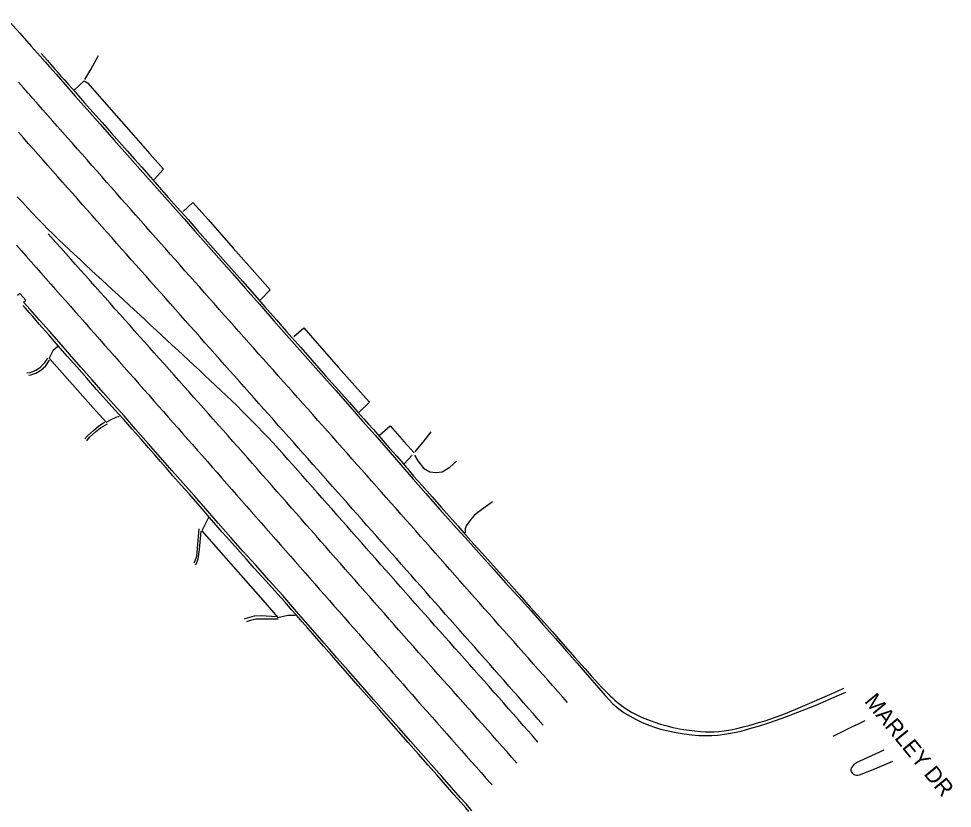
# Model space of a CAD drawing. Extents: x 1970211 to 1973046, y 801032 to 804001.
# Drawn here: x 1970390.1 to 1970705.8, y 803591.8 to 803858.6 of the extents above; entities that cross this region are included whole.
import ezdxf

# ---------------------------------------------------------------- set-up
doc = ezdxf.new("R2010")
doc.units = 0
for name, color, linetype in [('RD_EX_Conc', 7, 'Continuous'), ('RD_EX_Road', 7, 'Continuous'), ('RD_EX_Road_Paint', 7, 'Continuous'), ('RD_TX_RoadID', 7, 'Continuous')]:
    doc.layers.add(name, color=color, linetype=linetype)

msp = doc.modelspace()

# ---------------------------------------------------------------- linework, layer by layer
at = {"layer": 'RD_EX_Conc'}
for points in [[(1970397.74, 803846.86), (1970399.84, 803844.44), (1970400.97, 803843.15), (1970401.68, 803842.35), (1970402.51, 803841.4), (1970403.45, 803840.35), (1970404.45, 803839.23), (1970405.61, 803837.94), (1970407.04, 803836.34), (1970408.36, 803834.84), (1970409.23, 803833.84), (1970410.36, 803832.54), (1970412.45, 803830.16), (1970415.21, 803827.03), (1970418.35, 803823.47), (1970421.48, 803819.94), (1970424.23, 803816.85), (1970426.78, 803814), (1970429.31, 803811.14), (1970431.75, 803808.39), (1970434.01, 803805.84), (1970436.21, 803803.34), (1970438.48, 803800.75), (1970440.71, 803798.23), (1970442.77, 803795.92), (1970444.91, 803793.51), (1970447.4, 803790.7), (1970450.63, 803787.04), (1970454.98, 803782.09), (1970460.15, 803776.25), (1970465.78, 803769.88), (1970470.62, 803764.42), (1970473.38, 803761.29), (1970475.22, 803759.2), (1970477.28, 803756.84), (1970479.22, 803754.62), (1970480.69, 803752.95), (1970482.51, 803750.9), (1970485.49, 803747.52), (1970489.38, 803743.12), (1970493.92, 803737.97), (1970498.36, 803732.94), (1970501.95, 803728.88), (1970504.75, 803725.72), (1970506.79, 803723.43), (1970508.42, 803721.61), (1970509.97, 803719.87), (1970511.57, 803718.05), (1970513.36, 803716.02), (1970515.44, 803713.63), (1970517.95, 803710.76), (1970520.12, 803708.29), (1970521.16, 803707.09), (1970521.69, 803706.47), (1970522.29, 803705.71), (1970523.67, 803704.08), (1970526.52, 803700.83), (1970529.93, 803696.99), (1970532.98, 803693.55), (1970535.82, 803690.35), (1970538.6, 803687.19), (1970541.33, 803684.09), (1970544.04, 803681.09), (1970546.8, 803678.06), (1970549.7, 803674.86), (1970552.75, 803671.45), (1970555.98, 803667.82), (1970559.42, 803663.94), (1970563.1, 803659.8), (1970566.85, 803655.59), (1970570.46, 803651.51), (1970574.16, 803647.33), (1970578.16, 803642.81), (1970581.61, 803638.89), (1970583.69, 803636.56), (1970585, 803635.11), (1970586.15, 803633.87), (1970587.2, 803632.78), (1970588.18, 803631.76), (1970589.12, 803630.8), (1970590.01, 803629.92), (1970590.86, 803629.11), (1970591.67, 803628.36), (1970592.63, 803627.55), (1970593.92, 803626.53), (1970595.49, 803625.42), (1970597.31, 803624.33), (1970599.18, 803623.34), (1970600.94, 803622.53), (1970602.76, 803621.78), (1970604.83, 803621), (1970607.08, 803620.26), (1970609.4, 803619.62), (1970611.35, 803619.15), (1970612.52, 803618.88), (1970613.54, 803618.7), (1970615.05, 803618.45), (1970616.87, 803618.19), (1970618.79, 803617.98), (1970620.68, 803617.81), (1970622.4, 803617.69), (1970623.94, 803617.63), (1970625.29, 803617.66), (1970626.76, 803617.78), (1970628.64, 803618.02), (1970630.78, 803618.37), (1970632.99, 803618.81), (1970635.13, 803619.31), (1970637.05, 803619.8), (1970638.86, 803620.31), (1970640.72, 803620.87), (1970642.49, 803621.41), (1970644.06, 803621.91), (1970645.99, 803622.58), (1970648.83, 803623.65), (1970652.88, 803625.28), (1970658.46, 803627.62), (1970666.94, 803631.36), (1970669.16, 803632.36)], [(1970408.93, 803834.46), (1970412.28, 803837.6), (1970413.37, 803836.88), (1970418.27, 803831.36), (1970422.37, 803826.76), (1970428.98, 803819.24), (1970434.54, 803812.97), (1970439.09, 803807.8), (1970435.92, 803804.21)], [(1970445.78, 803793.44), (1970449.04, 803796.5), (1970454.16, 803790.74), (1970462.68, 803781.09), (1970471.79, 803770.78), (1970475.16, 803766.95), (1970471.88, 803763.62)], [(1970542.33, 803590.69), (1970541.29, 803591.93), (1970539.64, 803593.85), (1970537.32, 803596.5), (1970534.41, 803599.79), (1970531.48, 803603.11), (1970528.57, 803606.41), (1970525.36, 803610.06), (1970521.88, 803614.01), (1970518.55, 803617.78), (1970515.41, 803621.35), (1970512.11, 803625.09), (1970508.59, 803629.06), (1970504.93, 803633.2), (1970501.26, 803637.36), (1970498.25, 803640.8), (1970495.87, 803643.54), (1970493.22, 803646.57), (1970490.29, 803649.92), (1970487.85, 803652.72), (1970486.03, 803654.84), (1970484.78, 803656.28), (1970483.93, 803657.23), (1970482.43, 803658.92), (1970480.19, 803661.46), (1970477.68, 803664.28), (1970474.99, 803667.26), (1970472.37, 803670.16), (1970469.8, 803672.99), (1970467.04, 803676.08), (1970464.09, 803679.39), (1970461.37, 803682.44), (1970458.94, 803685.14), (1970456.93, 803687.43), (1970455.34, 803689.3), (1970454.02, 803690.84), (1970452.97, 803692.05), (1970452.16, 803692.98), (1970451.46, 803693.79), (1970450.02, 803695.44), (1970447.76, 803698.01), (1970445.13, 803700.98), (1970442.32, 803704.15), (1970439.96, 803706.83), (1970438.07, 803708.99), (1970436.16, 803711.18), (1970434.09, 803713.55), (1970431.52, 803716.48), (1970428.49, 803719.91), (1970425.54, 803723.24), (1970422.71, 803726.41), (1970419.71, 803729.76), (1970416.51, 803733.36), (1970413.2, 803737.1), (1970409.83, 803740.93), (1970406.59, 803744.59), (1970403.49, 803748.09), (1970400.29, 803751.74), (1970397.11, 803755.39), (1970394.9, 803757.93), (1970393.66, 803759.36), (1970392.32, 803760.87), (1970391.56, 803761.72)], [(1970483.18, 803751.16), (1970486.5, 803754.09), (1970491.07, 803748.92), (1970498.31, 803740.77), (1970506.58, 803731.41), (1970508.74, 803728.98), (1970505.11, 803725.56)], [(1970403.37, 803747.85), (1970401.69, 803746.37), (1970400.77, 803744.6), (1970400.41, 803743.93), (1970408.34, 803734.98), (1970415.23, 803727.26), (1970419.7, 803722.23), (1970421.15, 803723.01), (1970423.11, 803723.99), (1970424.27, 803724.34)], [(1970399.93, 803743.95), (1970398.77, 803742.2), (1970397.17, 803740.52), (1970395.92, 803739.72), (1970393.94, 803738.98), (1970392.96, 803738.88)], [(1970512.08, 803717.85), (1970515.71, 803721.08), (1970520.48, 803715.65), (1970523.85, 803711.87)], [(1970523.19, 803711.1), (1970520.42, 803708.2)], [(1970523.98, 803711.1), (1970525.08, 803709.18), (1970527.01, 803706.69), (1970529.18, 803705.54), (1970531.34, 803705.25), (1970533.32, 803705.44), (1970535.86, 803707.09), (1970538.18, 803709.04)], [(1970550.35, 803695.4), (1970544.96, 803691.36), (1970544.08, 803690.61), (1970542.92, 803689.27), (1970541.46, 803687.28), (1970541.06, 803686.2), (1970541.05, 803684.85)], [(1970454.33, 803690.05), (1970452.11, 803685.61), (1970457.75, 803679.18), (1970466.02, 803669.71), (1970472.67, 803662.15), (1970477.77, 803656.24), (1970481.15, 803657.04), (1970483.62, 803657.08)], [(1970685.55, 803607.64), (1970679.51, 803605.06), (1970674.34, 803603), (1970673.83, 803602.92), (1970673.38, 803602.92), (1970672.99, 803603), (1970672.66, 803603.14), (1970672.36, 803603.35), (1970672.1, 803603.59), (1970671.88, 803603.88), (1970671.68, 803604.2), (1970671.56, 803604.57), (1970671.58, 803604.96), (1970671.72, 803605.39), (1970672, 803605.86), (1970672.34, 803606.31), (1970672.69, 803606.69), (1970673.05, 803607.01), (1970673.42, 803607.27), (1970678.6, 803609.66), (1970682.8, 803611.55)]]:
    msp.add_lwpolyline(points, dxfattribs=at)
at = {"layer": 'RD_EX_Road'}
for points in [[(1970386.18, 803858.6), (1970390.49, 803853.69), (1970394.36, 803849.33), (1970397.36, 803845.97), (1970399.07, 803844.04), (1970400.53, 803842.38), (1970402.79, 803839.82), (1970405.74, 803836.48), (1970409.25, 803832.47), (1970413.25, 803827.91), (1970417.69, 803822.91), (1970422.31, 803817.7), (1970426.9, 803812.51), (1970431.23, 803807.63), (1970435.05, 803803.35), (1970438.67, 803799.31), (1970442.38, 803795.13), (1970446.09, 803790.93), (1970449.71, 803786.8), (1970453.52, 803782.48), (1970457.77, 803777.69), (1970462.27, 803772.62), (1970466.82, 803767.46), (1970471.51, 803762.12), (1970476.45, 803756.53), (1970481.62, 803750.67), (1970487.04, 803744.53), (1970492.41, 803738.47), (1970497.43, 803732.81), (1970502.11, 803727.55), (1970506.44, 803722.66), (1970510.66, 803717.85), (1970515.01, 803712.85), (1970519.34, 803707.85), (1970523.51, 803703.04), (1970527.79, 803698.16), (1970532.44, 803692.91), (1970537.28, 803687.51), (1970542.1, 803682.15), (1970546.67, 803677.06), (1970550.77, 803672.49), (1970554.77, 803668.04), (1970559.02, 803663.32), (1970563.36, 803658.49), (1970567.61, 803653.73), (1970571.66, 803649.15), (1970575.41, 803644.87), (1970578.93, 803640.81), (1970582.29, 803636.92), (1970585.47, 803633.25), (1970588.45, 803629.87), (1970591.04, 803627.13), (1970593.07, 803625.36), (1970594.9, 803624.1), (1970596.88, 803622.89), (1970598.88, 803621.8), (1970600.76, 803620.9), (1970602.68, 803620.11), (1970604.79, 803619.33), (1970607.13, 803618.6), (1970609.73, 803617.94), (1970612.44, 803617.38), (1970615.12, 803616.93), (1970617.7, 803616.61), (1970620.13, 803616.43), (1970622.4, 803616.37), (1970624.49, 803616.41), (1970626.56, 803616.55), (1970628.72, 803616.83), (1970630.82, 803617.19), (1970632.69, 803617.55), (1970634.36, 803617.92), (1970635.85, 803618.31), (1970637.65, 803618.83), (1970640.24, 803619.59), (1970643.75, 803620.71), (1970648.29, 803622.27), (1970653.6, 803624.25), (1970659.39, 803626.57), (1970667.65, 803630.11), (1970669.76, 803631.03)], [(1970412.53, 803838.01), (1970414.49, 803841.4), (1970417.19, 803846.17)], [(1970543.35, 803591), (1970542.49, 803592.06), (1970541.45, 803593.27), (1970539.46, 803595.51), (1970536.51, 803598.82), (1970533.19, 803602.56), (1970529.64, 803606.57), (1970526.11, 803610.55), (1970522.6, 803614.53), (1970518.74, 803618.87), (1970514.52, 803623.61), (1970510.15, 803628.55), (1970505.72, 803633.59), (1970501.53, 803638.37), (1970497.75, 803642.7), (1970495.1, 803645.73), (1970493.44, 803647.64), (1970491.18, 803650.22), (1970488.06, 803653.79), (1970484.1, 803658.32), (1970479.4, 803663.67), (1970474.75, 803668.92), (1970470.28, 803673.93), (1970465.98, 803678.72), (1970461.83, 803683.34), (1970457.63, 803688.09), (1970453.41, 803692.95), (1970449.45, 803697.49), (1970445.74, 803701.7), (1970441.98, 803705.95), (1970438.1, 803710.35), (1970433.98, 803715.05), (1970429.69, 803719.96), (1970425.77, 803724.39), (1970422.26, 803728.33), (1970418.68, 803732.35), (1970414.96, 803736.55), (1970411.16, 803740.86), (1970407.35, 803745.21), (1970403.81, 803749.26), (1970400.52, 803753.01), (1970397.23, 803756.73), (1970394.01, 803760.34), (1970391.79, 803762.82), (1970392.55, 803763.48), (1970390.5, 803765.74), (1970389.77, 803765.07)], [(1970393.6, 803738.14), (1970394.27, 803738.29), (1970395.99, 803738.85), (1970397.59, 803739.83), (1970399.35, 803741.28), (1970400.54, 803743.24)], [(1970412.56, 803716.66), (1970413.46, 803717.63), (1970415.43, 803719.47), (1970417.13, 803720.95), (1970418.59, 803721.91), (1970419.3, 803722.31)], [(1970413.14, 803716.02), (1970414.13, 803717.15), (1970416.09, 803719), (1970417.79, 803720.36), (1970420.18, 803721.71)], [(1970524.2, 803712.22), (1970525.06, 803713.32), (1970526.94, 803715.47), (1970529.63, 803719.05)], [(1970451.04, 803686.27), (1970450.48, 803679.66), (1970450.22, 803676.93), (1970449.67, 803675.36), (1970449.32, 803674.8)], [(1970449.94, 803674.11), (1970450.25, 803674.52), (1970450.84, 803676.07), (1970451.32, 803679.22), (1970451.84, 803685.42)], [(1970477.28, 803656.45), (1970472.11, 803656.88), (1970469.73, 803656.68), (1970466.66, 803655.81), (1970466.43, 803655.71)], [(1970477.89, 803655.68), (1970472.05, 803655.76), (1970470.29, 803655.69), (1970468.1, 803655.16), (1970467.18, 803654.85)]]:
    msp.add_lwpolyline(points, dxfattribs=at)
at = {"layer": 'RD_EX_Road_Paint'}
for points in [[(1970575.74, 803627.54), (1970574.08, 803629.41), (1970572.43, 803631.28), (1970570.77, 803633.15), (1970569.11, 803635.02), (1970567.45, 803636.89), (1970565.79, 803638.76), (1970564.13, 803640.63), (1970562.47, 803642.5), (1970560.82, 803644.37), (1970559.16, 803646.24), (1970557.5, 803648.11), (1970555.84, 803649.98), (1970554.18, 803651.85), (1970552.52, 803653.72), (1970550.86, 803655.59), (1970549.2, 803657.47), (1970547.55, 803659.34), (1970545.89, 803661.21), (1970544.24, 803663.08), (1970542.58, 803664.96), (1970540.92, 803666.83), (1970539.27, 803668.7), (1970537.61, 803670.58), (1970535.96, 803672.45), (1970534.3, 803674.32), (1970532.65, 803676.19), (1970530.99, 803678.07), (1970529.33, 803679.94), (1970527.68, 803681.81), (1970526.02, 803683.69), (1970524.37, 803685.56), (1970522.71, 803687.43), (1970521.05, 803689.31), (1970519.4, 803691.18), (1970517.74, 803693.05), (1970516.08, 803694.92), (1970514.43, 803696.79), (1970512.77, 803698.67), (1970511.11, 803700.54), (1970509.45, 803702.41), (1970507.8, 803704.28), (1970506.14, 803706.15), (1970504.48, 803708.02), (1970502.82, 803709.89), (1970501.16, 803711.76), (1970499.51, 803713.64), (1970497.85, 803715.51), (1970496.19, 803717.38), (1970494.53, 803719.25), (1970492.88, 803721.12), (1970491.22, 803722.99), (1970489.55, 803724.86), (1970487.89, 803726.72), (1970486.23, 803728.59), (1970484.56, 803730.46), (1970482.9, 803732.32), (1970481.24, 803734.19), (1970479.58, 803736.06), (1970477.91, 803737.92), (1970476.25, 803739.79), (1970474.59, 803741.66), (1970472.92, 803743.53), (1970471.26, 803745.39), (1970469.6, 803747.26), (1970467.94, 803749.13), (1970466.27, 803750.99), (1970464.61, 803752.86), (1970462.95, 803754.73), (1970461.29, 803756.6), (1970459.64, 803758.47), (1970457.98, 803760.34), (1970456.32, 803762.21), (1970454.66, 803764.09), (1970453, 803765.96), (1970451.35, 803767.83), (1970449.69, 803769.7), (1970448.03, 803771.57), (1970446.37, 803773.44), (1970444.71, 803775.31), (1970443.05, 803777.18), (1970441.4, 803779.05), (1970439.74, 803780.92), (1970438.08, 803782.79), (1970436.42, 803784.67), (1970434.77, 803786.54), (1970433.11, 803788.41), (1970431.46, 803790.29), (1970429.8, 803792.16), (1970428.15, 803794.03), (1970426.49, 803795.91), (1970424.83, 803797.78), (1970423.18, 803799.65), (1970421.52, 803801.53), (1970419.87, 803803.4), (1970418.21, 803805.27), (1970416.56, 803807.15), (1970414.9, 803809.02), (1970413.25, 803810.89), (1970411.59, 803812.77), (1970409.94, 803814.64), (1970408.29, 803816.52), (1970406.63, 803818.39), (1970404.98, 803820.27), (1970403.33, 803822.15), (1970401.67, 803824.02), (1970400.02, 803825.9), (1970398.37, 803827.77), (1970396.72, 803829.65), (1970395.06, 803831.53), (1970393.41, 803833.4), (1970391.76, 803835.28), (1970390.11, 803837.15)], [(1970567.46, 803619.94), (1970565.81, 803621.82), (1970564.16, 803623.7), (1970562.5, 803625.57), (1970560.85, 803627.45), (1970559.2, 803629.32), (1970557.54, 803631.2), (1970555.89, 803633.07), (1970554.24, 803634.95), (1970552.59, 803636.83), (1970550.93, 803638.7), (1970549.28, 803640.58), (1970547.63, 803642.45), (1970545.98, 803644.33), (1970544.32, 803646.2), (1970542.67, 803648.08), (1970541.01, 803649.95), (1970539.36, 803651.82), (1970537.7, 803653.7), (1970536.04, 803655.57), (1970534.39, 803657.44), (1970532.73, 803659.32), (1970531.08, 803661.19), (1970529.42, 803663.06), (1970527.77, 803664.94), (1970526.11, 803666.81), (1970524.46, 803668.68), (1970522.8, 803670.56), (1970521.14, 803672.43), (1970519.49, 803674.3), (1970517.83, 803676.18), (1970516.18, 803678.05), (1970514.52, 803679.92), (1970512.86, 803681.79), (1970511.21, 803683.67), (1970509.55, 803685.54), (1970507.9, 803687.41), (1970506.24, 803689.28), (1970504.58, 803691.16), (1970502.93, 803693.03), (1970501.27, 803694.9), (1970499.61, 803696.77), (1970497.95, 803698.64), (1970496.29, 803700.51), (1970494.63, 803702.38), (1970492.97, 803704.25), (1970491.31, 803706.12), (1970489.65, 803707.99), (1970487.99, 803709.86), (1970486.33, 803711.73), (1970484.67, 803713.6), (1970483.02, 803715.47), (1970481.36, 803717.34), (1970479.7, 803719.21), (1970478.03, 803721.08), (1970476.37, 803722.95), (1970474.71, 803724.81), (1970473.05, 803726.68), (1970471.39, 803728.55), (1970469.73, 803730.42), (1970468.07, 803732.29), (1970466.41, 803734.16), (1970464.75, 803736.03), (1970463.09, 803737.9), (1970461.43, 803739.76), (1970459.77, 803741.63), (1970458.11, 803743.5), (1970456.45, 803745.37), (1970454.79, 803747.24), (1970453.13, 803749.11), (1970451.47, 803750.98), (1970449.81, 803752.85), (1970448.15, 803754.72), (1970446.49, 803756.59), (1970444.83, 803758.46), (1970443.17, 803760.33), (1970441.51, 803762.2), (1970439.85, 803764.07), (1970438.19, 803765.94), (1970436.53, 803767.81), (1970434.87, 803769.68), (1970433.21, 803771.55), (1970431.55, 803773.42), (1970429.89, 803775.29), (1970428.23, 803777.15), (1970426.57, 803779.02), (1970424.91, 803780.89), (1970423.25, 803782.76), (1970421.59, 803784.63), (1970419.93, 803786.5), (1970418.27, 803788.37), (1970416.61, 803790.24), (1970414.95, 803792.11), (1970413.29, 803793.98), (1970411.64, 803795.85), (1970409.98, 803797.72), (1970408.32, 803799.6), (1970406.67, 803801.47), (1970405.01, 803803.34), (1970403.35, 803805.21), (1970401.7, 803807.09), (1970400.04, 803808.96), (1970398.38, 803810.83), (1970396.73, 803812.7), (1970395.07, 803814.58), (1970393.41, 803816.45), (1970391.76, 803818.32), (1970390.11, 803820.2)], [(1970565.69, 803614.2), (1970564.04, 803616.08), (1970562.39, 803617.95), (1970560.73, 803619.83), (1970559.08, 803621.7), (1970557.43, 803623.58), (1970555.77, 803625.45), (1970554.12, 803627.33), (1970552.47, 803629.2), (1970550.81, 803631.08), (1970549.16, 803632.96), (1970547.5, 803634.83), (1970545.84, 803636.69), (1970544.18, 803638.56), (1970542.52, 803640.43), (1970540.86, 803642.3), (1970539.2, 803644.17), (1970537.53, 803646.03), (1970535.87, 803647.9), (1970534.21, 803649.77), (1970532.55, 803651.64), (1970530.89, 803653.51), (1970529.23, 803655.37), (1970527.57, 803657.24), (1970525.9, 803659.11), (1970524.24, 803660.98), (1970522.58, 803662.85), (1970520.92, 803664.72), (1970519.27, 803666.59), (1970517.61, 803668.46), (1970515.96, 803670.34), (1970514.3, 803672.21), (1970512.64, 803674.08), (1970510.99, 803675.96), (1970509.33, 803677.83), (1970507.68, 803679.7), (1970506.02, 803681.58), (1970504.37, 803683.45), (1970502.71, 803685.32), (1970501.05, 803687.2), (1970499.4, 803689.07), (1970497.74, 803690.94), (1970496.09, 803692.82), (1970494.43, 803694.69), (1970492.78, 803696.56), (1970491.12, 803698.44), (1970489.47, 803700.31), (1970487.81, 803702.18), (1970486.16, 803704.06), (1970484.5, 803705.93), (1970482.84, 803707.8), (1970481.18, 803709.66), (1970479.51, 803711.53), (1970477.85, 803713.4), (1970476.17, 803715.24), (1970474.45, 803717.06), (1970472.73, 803718.88), (1970471, 803720.69), (1970469.25, 803722.46), (1970467.49, 803724.24), (1970465.73, 803726.02), (1970463.97, 803727.8), (1970462.16, 803729.51), (1970460.34, 803731.23), (1970458.52, 803732.95), (1970456.7, 803734.66), (1970454.89, 803736.38), (1970453.06, 803738.09), (1970451.23, 803739.79), (1970449.4, 803741.49), (1970447.57, 803743.2), (1970445.74, 803744.9), (1970443.91, 803746.6), (1970442.07, 803748.3), (1970440.24, 803750), (1970438.41, 803751.7), (1970436.58, 803753.4), (1970434.74, 803755.1), (1970432.91, 803756.8), (1970431.07, 803758.5), (1970429.24, 803760.19), (1970427.4, 803761.89), (1970425.57, 803763.59), (1970423.73, 803765.29), (1970421.9, 803766.99), (1970420.06, 803768.69), (1970418.23, 803770.38), (1970416.39, 803772.08), (1970414.56, 803773.78), (1970412.73, 803775.48), (1970410.89, 803777.18), (1970409.06, 803778.87), (1970407.24, 803780.59), (1970405.42, 803782.3), (1970403.6, 803784.02), (1970401.78, 803785.74), (1970400.02, 803787.51), (1970398.27, 803789.3), (1970396.52, 803791.08), (1970394.81, 803792.9), (1970393.1, 803794.73), (1970391.4, 803796.56), (1970389.69, 803798.38)], [(1970558.57, 803607.09), (1970556.92, 803608.97), (1970555.26, 803610.84), (1970553.61, 803612.71), (1970551.95, 803614.58), (1970550.29, 803616.46), (1970548.64, 803618.33), (1970546.98, 803620.2), (1970545.32, 803622.07), (1970543.65, 803623.93), (1970541.99, 803625.8), (1970540.33, 803627.67), (1970538.67, 803629.54), (1970537.01, 803631.4), (1970535.34, 803633.27), (1970533.68, 803635.14), (1970532.02, 803637.01), (1970530.36, 803638.87), (1970528.69, 803640.74), (1970527.03, 803642.61), (1970525.37, 803644.48), (1970523.71, 803646.34), (1970522.05, 803648.21), (1970520.38, 803650.08), (1970518.72, 803651.95), (1970517.07, 803653.82), (1970515.42, 803655.7), (1970513.77, 803657.58), (1970512.12, 803659.45), (1970510.47, 803661.33), (1970508.82, 803663.21), (1970507.17, 803665.09), (1970505.52, 803666.97), (1970503.87, 803668.84), (1970502.22, 803670.72), (1970500.57, 803672.6), (1970498.92, 803674.48), (1970497.27, 803676.36), (1970495.62, 803678.23), (1970493.97, 803680.11), (1970492.32, 803681.99), (1970490.67, 803683.87), (1970489.02, 803685.75), (1970487.37, 803687.63), (1970485.72, 803689.5), (1970484.07, 803691.38), (1970482.42, 803693.26), (1970480.77, 803695.14), (1970479.12, 803697.02), (1970477.47, 803698.89), (1970475.82, 803700.77), (1970474.17, 803702.65), (1970472.52, 803704.53), (1970470.87, 803706.41), (1970469.22, 803708.28), (1970467.57, 803710.16), (1970465.92, 803712.04), (1970464.26, 803713.92), (1970462.6, 803715.78), (1970460.94, 803717.65), (1970459.28, 803719.52), (1970457.61, 803721.39), (1970455.95, 803723.25), (1970454.29, 803725.12), (1970452.63, 803726.99), (1970450.97, 803728.86), (1970449.3, 803730.72), (1970447.64, 803732.59), (1970445.98, 803734.46), (1970444.32, 803736.33), (1970442.66, 803738.19), (1970440.99, 803740.06), (1970439.33, 803741.93), (1970437.67, 803743.8), (1970436.01, 803745.67), (1970434.35, 803747.53), (1970432.69, 803749.4), (1970431.02, 803751.27), (1970429.36, 803753.14), (1970427.7, 803755), (1970426.04, 803756.87), (1970424.38, 803758.74), (1970422.71, 803760.61), (1970421.05, 803762.47), (1970419.39, 803764.34), (1970417.72, 803766.21), (1970416.06, 803768.07), (1970414.39, 803769.93), (1970412.73, 803771.8), (1970411.06, 803773.66), (1970409.4, 803775.53), (1970407.73, 803777.39), (1970406.07, 803779.26), (1970404.4, 803781.12), (1970402.73, 803782.98), (1970401.07, 803784.85), (1970400.17, 803785.85)], [(1970389.41, 803782.06), (1970391.06, 803780.19), (1970392.72, 803778.31), (1970394.37, 803776.44), (1970396.03, 803774.57), (1970397.69, 803772.69), (1970399.34, 803770.82), (1970401, 803768.95), (1970402.65, 803767.07), (1970404.31, 803765.2), (1970405.96, 803763.33), (1970407.62, 803761.45), (1970409.27, 803759.58), (1970410.93, 803757.71), (1970412.59, 803755.83), (1970414.24, 803753.96), (1970415.9, 803752.09), (1970417.55, 803750.21), (1970419.21, 803748.34), (1970420.86, 803746.47), (1970422.52, 803744.59), (1970424.17, 803742.72), (1970425.83, 803740.85), (1970427.48, 803738.97), (1970429.14, 803737.1), (1970430.8, 803735.23), (1970432.45, 803733.35), (1970434.11, 803731.48), (1970435.76, 803729.61), (1970437.42, 803727.73), (1970439.07, 803725.86), (1970440.72, 803723.98), (1970442.37, 803722.1), (1970444.02, 803720.22), (1970445.67, 803718.35), (1970447.32, 803716.47), (1970448.98, 803714.59), (1970450.63, 803712.72), (1970452.28, 803710.84), (1970453.93, 803708.96), (1970455.58, 803707.08), (1970457.23, 803705.21), (1970458.88, 803703.33), (1970460.53, 803701.45), (1970462.18, 803699.57), (1970463.83, 803697.7), (1970465.48, 803695.82), (1970467.14, 803693.94), (1970468.79, 803692.06), (1970470.44, 803690.19), (1970472.09, 803688.31), (1970473.74, 803686.43), (1970475.39, 803684.56), (1970477.04, 803682.68), (1970478.69, 803680.8), (1970480.34, 803678.92), (1970481.99, 803677.05), (1970483.65, 803675.17), (1970485.3, 803673.29), (1970486.95, 803671.41), (1970488.6, 803669.54), (1970490.25, 803667.66), (1970491.9, 803665.78), (1970493.55, 803663.9), (1970495.2, 803662.03), (1970496.85, 803660.15), (1970498.5, 803658.27), (1970500.15, 803656.4), (1970501.81, 803654.52), (1970503.46, 803652.64), (1970505.11, 803650.76), (1970506.76, 803648.89), (1970508.41, 803647.01), (1970510.06, 803645.13), (1970511.71, 803643.25), (1970513.36, 803641.38), (1970515.01, 803639.5), (1970516.66, 803637.62), (1970518.31, 803635.74), (1970519.97, 803633.87), (1970521.62, 803631.99), (1970523.27, 803630.11), (1970524.92, 803628.24), (1970526.58, 803626.36), (1970528.23, 803624.49), (1970529.89, 803622.62), (1970531.55, 803620.75), (1970533.2, 803618.87), (1970534.86, 803617), (1970536.52, 803615.13), (1970538.17, 803613.26), (1970539.83, 803611.39), (1970541.49, 803609.51), (1970543.14, 803607.64), (1970544.8, 803605.77), (1970546.46, 803603.9), (1970548.11, 803602.03), (1970549.77, 803600.15), (1970550.18, 803599.69)], [(1970676.25, 803621.33), (1970673.99, 803620.27), (1970671.74, 803619.18), (1970669.5, 803618.09), (1970667.25, 803617), (1970665.35, 803616.08)]]:
    msp.add_lwpolyline(points, dxfattribs=at)

# ---------------------------------------------------------------- texts
at = {"layer": 'RD_TX_RoadID'}
msp.add_text('MARLEY DR', height=5.4, rotation=309.2924, dxfattribs=at).set_placement((1970675.85, 803627.86))

doc.saveas('drawing.dxf')
